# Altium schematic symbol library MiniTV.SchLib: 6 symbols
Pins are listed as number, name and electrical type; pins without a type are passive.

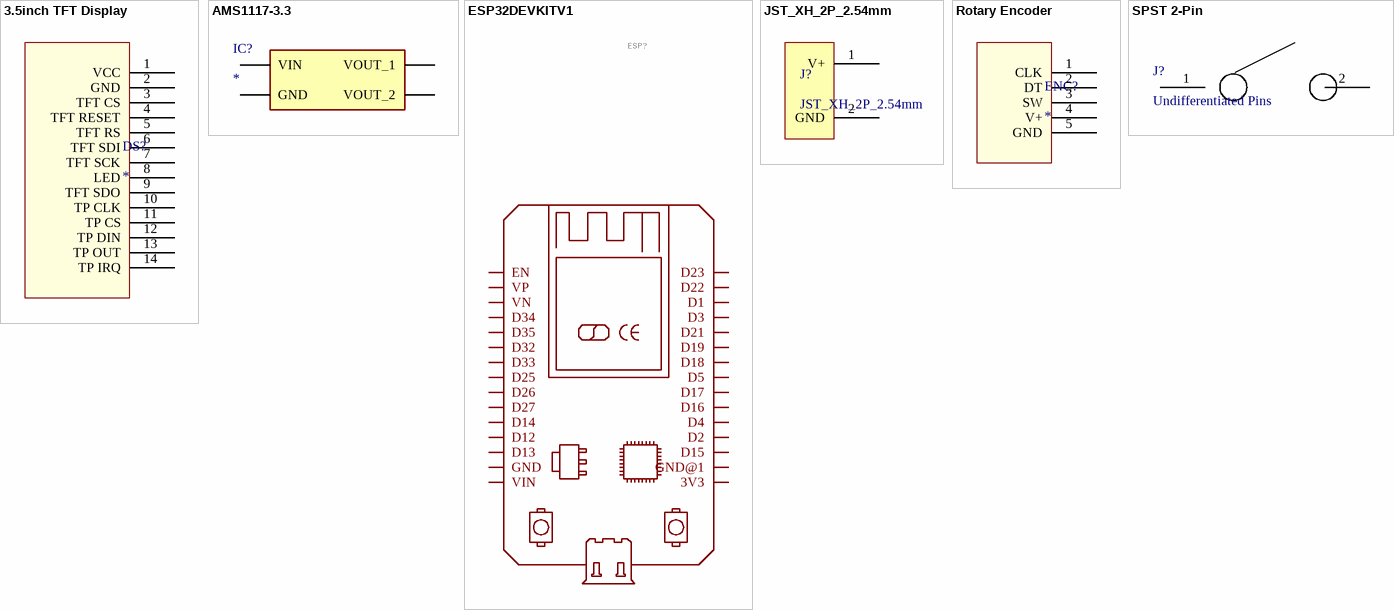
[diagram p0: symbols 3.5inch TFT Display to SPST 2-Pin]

## 3.5inch TFT Display
designator DS?
footprint 3.5inch SPI Display
pins: 1 VCC, 2 GND, 3 TFT CS, 4 TFT RESET, 5 TFT RS, 6 TFT SDI, 7 TFT SCK, 8 LED, 9 TFT SDO, 10 TP CLK, 11 TP CS, 12 TP DIN, 13 TP OUT, 14 TP IRQ

## AMS1117-3.3
designator IC?
Integrated Circuit; Manufacturer_Name: Advanced Monolithic Systems; Manufacturer_Part_Number: AMS1117-3.3
footprint SOT229P700X180-4N
pins: 1 GND, 2 VOUT_1, 3 VIN, 4 VOUT_2

## ESP32DEVKITV1
designator ESP?, comment https://github.com/shridattdudhat  (value not drawn)
GateName_1: G$1; SymbolName_1: ESP32-DEVKITV1; DeviceSetName: ESP32DEVKITV1
footprint ESP32-DEVKITV1
pins: 3V3 (io), D1 (io), D2 (io), D3 (io), D4 (io), D5 (io), D12 (io), D13 (io), D14 (io), D15 (io), D16 (io), D17 (io), D18 (io), D19 (io), D21 (io), D22 (io), D23 (io), D25 (io), D26 (io), D27 (io), D32 (io), D33 (io), D34 (io), D35 (io), EN (io), GND (io), GND@1 (io), VIN (io), VN (io), VP (io)

## JST_XH_2P_2.54mm
designator J?
footprint JST_XH_2P_2.54mm
pins: 1 V+, 2 GND

## Rotary Encoder
designator ENC?
footprint Rotary Encoder
pins: 1 CLK, 2 DT, 3 SW, 4 V+, 5 GND

## SPST 2-Pin
designator J?, comment Undifferentiated Pins
footprint 2-Pin 2.54mm
pins: 1, 2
